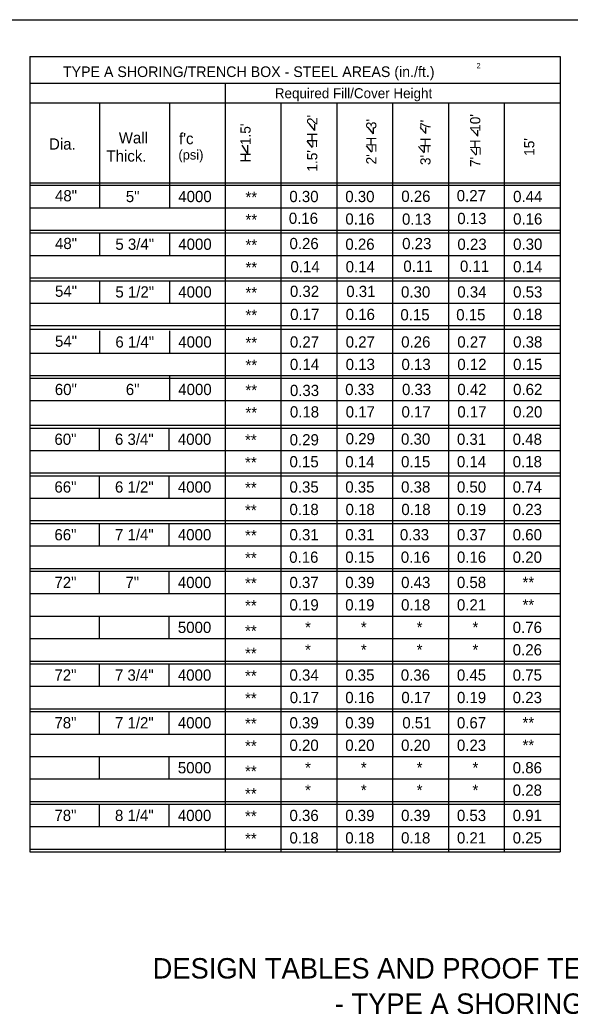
# Model space of a CAD drawing. Extents: x -22562 to -18409, y 3991 to 7171.
# Drawn here: x -20178.4 to -20023, y 4289.5 to 4570.4 of the extents above; entities that cross this region are included whole.
import ezdxf

# ---------------------------------------------------------------- set-up
doc = ezdxf.new("R2010")
doc.units = 0
for name, color, linetype in [('1', 7, 'Continuous'), ('2', 7, 'Continuous'), ('3', 7, 'Continuous'), ('4', 7, 'Continuous')]:
    doc.layers.add(name, color=color, linetype=linetype)

msp = doc.modelspace()

# ---------------------------------------------------------------- linework, layer by layer
at = {"layer": '1'}
for p, q in [((-20095.05, 4539.1), (-20096.61, 4540.87)), ((-20095.05, 4539.1), (-20095.05, 4540.86)), ((-20078.47, 4538.16), (-20080.04, 4539.93)), ((-20078.47, 4538.16), (-20078.47, 4539.92)), ((-20063.73, 4538.22), (-20065.3, 4539.99)), ((-20063.73, 4538.22), (-20063.73, 4539.97)), ((-20049.01, 4537.47), (-20050.58, 4539.24)), ((-20049.01, 4537.47), (-20049.01, 4539.22)), ((-20114.01, 4532.54), (-20115.57, 4534.97)), ((-20114.01, 4532.54), (-20114.01, 4534.95)), ((-20095.7, 4534.3), (-20097.27, 4536.07)), ((-20078.93, 4533.02), (-20080.49, 4534.79)), ((-20064.19, 4532.8), (-20065.75, 4534.57)), ((-20049.47, 4532.11), (-20051.03, 4533.87))]:
    msp.add_line(p, q, dxfattribs=at)
at = {"layer": '2'}
for p, q in [((-20344.85, 4570.37), (-19558.85, 4570.37)), ((-20175.6, 4560.02), (-20175.6, 4335.28)), ((-20175.6, 4560.02), (-20025.8, 4560.02)), ((-20025.8, 4560.02), (-20025.8, 4335.28)), ((-20175.6, 4552.45), (-20025.8, 4552.45)), ((-20120.41, 4552.45), (-20120.41, 4335.28)), ((-20175.6, 4546.95), (-20025.8, 4546.95)), ((-20155.88, 4546.95), (-20155.88, 4520.26)), ((-20136.17, 4546.95), (-20136.17, 4520.15)), ((-20104.64, 4546.95), (-20104.64, 4335.28)), ((-20088.87, 4546.95), (-20088.87, 4335.28)), ((-20073.1, 4546.95), (-20073.1, 4335.28)), ((-20057.34, 4546.95), (-20057.34, 4335.28)), ((-20041.57, 4546.95), (-20041.57, 4335.28)), ((-20175.6, 4524.43), (-20175.6, 4415.32)), ((-20175.6, 4524.37), (-20025.8, 4524.37)), ((-20175.6, 4523.68), (-20025.8, 4523.68)), ((-20155.88, 4524.43), (-20155.88, 4517.3)), ((-20155.88, 4523.64), (-20155.88, 4517.3)), ((-20136.17, 4524.43), (-20136.17, 4517.3)), ((-20136.17, 4523.64), (-20136.17, 4517.3)), ((-20175.6, 4517.3), (-20025.8, 4517.3)), ((-20175.6, 4510.95), (-20025.8, 4510.95)), ((-20175.6, 4510.95), (-20025.8, 4510.95)), ((-20175.6, 4510.16), (-20025.8, 4510.16)), ((-20155.88, 4510.16), (-20155.88, 4503.82)), ((-20136.17, 4510.16), (-20136.17, 4503.82)), ((-20175.6, 4503.82), (-20025.8, 4503.82)), ((-20175.6, 4497.47), (-20025.8, 4497.47)), ((-20175.6, 4497.47), (-20025.8, 4497.47)), ((-20175.6, 4496.68), (-20025.8, 4496.68)), ((-20155.88, 4496.68), (-20155.88, 4490.33)), ((-20136.17, 4496.68), (-20136.17, 4490.33)), ((-20175.6, 4490.33), (-20025.8, 4490.33)), ((-20175.6, 4483.99), (-20025.8, 4483.99)), ((-20175.6, 4483.99), (-20025.8, 4483.99)), ((-20175.45, 4483.02), (-20025.65, 4483.02)), ((-20155.88, 4482.55), (-20155.88, 4476.2)), ((-20136.17, 4482.55), (-20136.17, 4476.2)), ((-20175.6, 4476.2), (-20025.8, 4476.2)), ((-20175.6, 4469.86), (-20025.8, 4469.86)), ((-20175.6, 4469.86), (-20025.8, 4469.86)), ((-20136.17, 4469.92), (-20136.17, 4462.79)), ((-20175.6, 4469.17), (-20025.8, 4469.17)), ((-20175.6, 4462.79), (-20025.79, 4462.79)), ((-20175.71, 4455.85), (-20025.91, 4455.85)), ((-20175.71, 4455.06), (-20025.91, 4455.06)), ((-20156, 4455.06), (-20156, 4448.71)), ((-20136.29, 4455.06), (-20136.29, 4448.71)), ((-20175.71, 4448.71), (-20025.91, 4448.71)), ((-20175.71, 4442.37), (-20025.91, 4442.37)), ((-20175.71, 4442.36), (-20025.91, 4442.36)), ((-20175.71, 4441.57), (-20175.71, 4441.57)), ((-20175.71, 4441.57), (-20025.91, 4441.57)), ((-20156, 4441.57), (-20156, 4435.23)), ((-20136.29, 4441.57), (-20136.29, 4435.23)), ((-20175.71, 4435.23), (-20025.91, 4435.23)), ((-20175.71, 4428.88), (-20025.91, 4428.88)), ((-20175.71, 4428.88), (-20025.91, 4428.88)), ((-20175.71, 4428.08), (-20025.91, 4428.08)), ((-20156, 4428.08), (-20156, 4421.74)), ((-20136.29, 4428.08), (-20136.29, 4421.74)), ((-20175.71, 4421.74), (-20025.91, 4421.74)), ((-20175.71, 4415.39), (-20025.91, 4415.39)), ((-20175.71, 4415.39), (-20025.91, 4415.39)), ((-20175.71, 4414.6), (-20025.91, 4414.6)), ((-20156, 4414.6), (-20156, 4408.26)), ((-20136.29, 4414.6), (-20136.29, 4408.26)), ((-20175.71, 4408.26), (-20025.91, 4408.26)), ((-20175.71, 4401.91), (-20025.91, 4401.91)), ((-20156, 4401.91), (-20156, 4395.57)), ((-20136.29, 4401.91), (-20136.29, 4395.57)), ((-20175.71, 4395.57), (-20025.91, 4395.57)), ((-20175.71, 4389.22), (-20025.91, 4389.22)), ((-20175.71, 4389.22), (-20025.91, 4389.22)), ((-20175.71, 4388.43), (-20025.91, 4388.43)), ((-20156, 4388.43), (-20156, 4382.09)), ((-20136.29, 4388.43), (-20136.29, 4382.09)), ((-20175.71, 4382.09), (-20025.91, 4382.09)), ((-20175.71, 4375.74), (-20025.91, 4375.74)), ((-20175.71, 4375.74), (-20025.91, 4375.74)), ((-20175.71, 4374.95), (-20025.91, 4374.95)), ((-20156, 4374.95), (-20156, 4368.6)), ((-20136.29, 4374.95), (-20136.29, 4368.6)), ((-20175.71, 4368.6), (-20025.91, 4368.6)), ((-20175.71, 4362.26), (-20025.91, 4362.26)), ((-20156, 4362.26), (-20156, 4355.91)), ((-20136.29, 4362.26), (-20136.29, 4355.91)), ((-20175.71, 4355.91), (-20025.91, 4355.91)), ((-20175.71, 4349.56), (-20025.91, 4349.56)), ((-20175.71, 4349.56), (-20025.91, 4349.56)), ((-20175.71, 4348.78), (-20025.91, 4348.78)), ((-20156, 4348.78), (-20156, 4342.43)), ((-20136.29, 4348.78), (-20136.29, 4342.43)), ((-20175.71, 4342.43), (-20025.91, 4342.43)), ((-20175.71, 4336.08), (-20025.91, 4336.08)), ((-20175.6, 4335.28), (-20025.8, 4335.28))]:
    msp.add_line(p, q, dxfattribs=at)

# ---------------------------------------------------------------- texts
at = {"layer": '1'}
for s, height, p in [("f'c", 3.172, (-20133.46, 4535.24)), ('Thick.', 3.172, (-20153.95, 4530.33)), ('(psi)', 2.719, (-20133.62, 4530.9)), ('DESIGN TABLES AND PROOF TEST LOAD TABLE FOR CIRCULAR PIPES', 5.7669, (-20140.9, 4299.52)), ('- TYPE A SHORING/TRENCH BOX INSTALLATION', 5.7669, (-20089.43, 4289.54))]:
    msp.add_text(s, height=height, dxfattribs=at).set_placement(p)
for s, height, p in [("15'", 2.883, (-20033.06, 4531.95)), ('=', 2.88, (-20093.76, 4534.27)), ('=', 2.88, (-20076.98, 4532.99)), ('=', 2.88, (-20062.24, 4532.78)), ('=', 2.88, (-20047.52, 4532.08))]:
    msp.add_text(s, height=height, rotation=90, dxfattribs=at).set_placement(p)
at = {"layer": '2'}
for s, height, p in [('TYPE A SHORING/TRENCH BOX - STEEL AREAS (in./ft.)', 3, (-20166.25, 4554.22)), ('2', 1.5, (-20049.39, 4556.67)), ('Required Fill/Cover Height', 2.8357, (-20106.38, 4548.23)), ('Dia.', 3.172, (-20170.18, 4533.71)), ('Wall', 3.172, (-20150.47, 4535.46))]:
    msp.add_text(s, height=height, dxfattribs=at).set_placement(p)
at = {"layer": '3'}
for s, height, p in [('**', 3.173, (-20114.68, 4518.67)), ('0.30', 3.172, (-20102.28, 4518.88)), ('0.30', 3.172, (-20086.48, 4518.88)), ('0.26', 3.172, (-20070.65, 4518.95)), ('0.27', 3.174, (-20054.99, 4519.13)), ('0.44', 3.173, (-20039.06, 4518.88)), ('**', 3.173, (-20114.68, 4512.32)), ('0.16', 3.172, (-20102.43, 4512.73)), ('0.16', 3.172, (-20086.45, 4512.54)), ('0.13', 3.173, (-20070.45, 4512.49)), ('0.13', 3.173, (-20054.84, 4512.67)), ('0.16', 3.173, (-20039.06, 4512.54)), ('0.26', 3.172, (-20102.24, 4505.59)), ('0.26', 3.172, (-20086.45, 4505.4)), ('0.23', 3.174, (-20070.41, 4505.58)), ('0.23', 3.174, (-20054.8, 4505.39)), ('0.30', 3.173, (-20039.06, 4505.4)), ('**', 3.173, (-20114.68, 4505.18)), ('**', 3.173, (-20114.68, 4498.83)), ('0.14', 3.172, (-20101.97, 4499.05)), ('0.14', 3.172, (-20086.37, 4499.05)), ('0.11', 3.173, (-20070.07, 4499.18)), ('0.11', 3.173, (-20054.09, 4499.18)), ('0.14', 3.174, (-20039.06, 4499.05)), ('**', 3.173, (-20114.68, 4491.7)), ('0.32', 3.172, (-20102.12, 4492.09)), ('0.31', 3.173, (-20086.2, 4492.06)), ('0.30', 3.172, (-20070.73, 4491.92)), ('0.34', 3.173, (-20054.83, 4491.92)), ('0.53', 3.173, (-20039.06, 4491.92)), ('**', 3.173, (-20114.68, 4485.35)), ('0.17', 3.172, (-20102.05, 4485.57)), ('0.16', 3.173, (-20086.36, 4485.57)), ('0.15', 3.173, (-20070.9, 4485.47)), ('0.15', 3.173, (-20055.13, 4485.47)), ('0.18', 3.173, (-20039.06, 4485.57)), ('**', 3.173, (-20114.68, 4477.57)), ('0.27', 3.173, (-20102.13, 4477.79)), ('0.27', 3.173, (-20086.36, 4477.79)), ('0.26', 3.172, (-20070.68, 4477.79)), ('0.27', 3.173, (-20054.83, 4477.79)), ('0.27', 3.173, (-20054.83, 4477.79)), ('0.38', 3.173, (-20039.06, 4477.79)), ('**', 3.173, (-20114.68, 4471.22)), ('0.14', 3.172, (-20102.13, 4471.44)), ('0.13', 3.173, (-20086.36, 4471.44)), ('0.13', 3.172, (-20070.6, 4471.44)), ('0.12', 3.173, (-20054.83, 4471.44)), ('0.15', 3.173, (-20039.06, 4471.44)), ('**', 3.173, (-20114.69, 4464.15)), ('0.33', 3.172, (-20102.12, 4464.09)), ('0.33', 3.172, (-20086.5, 4464.37)), ('0.33', 3.172, (-20070.45, 4464.37)), ('0.42', 3.173, (-20054.82, 4464.37)), ('0.62', 3.173, (-20039.06, 4464.37)), ('**', 3.173, (-20114.69, 4457.81)), ('0.18', 3.172, (-20102.13, 4458.03)), ('0.17', 3.172, (-20086.36, 4458.03)), ('0.17', 3.172, (-20070.59, 4458.03)), ('0.17', 3.173, (-20054.82, 4458.03)), ('0.20', 3.173, (-20039.06, 4458.03)), ('**', 3.173, (-20114.8, 4450.08)), ('0.29', 3.173, (-20102.19, 4450.15)), ('0.29', 3.173, (-20086.36, 4450.44)), ('0.30', 3.172, (-20070.73, 4450.34)), ('0.31', 3.173, (-20054.94, 4450.3)), ('0.48', 3.173, (-20039.17, 4450.3)), ('**', 3.173, (-20114.8, 4443.73)), ('0.15', 3.172, (-20102.24, 4443.95)), ('0.14', 3.172, (-20086.48, 4443.95)), ('0.15', 3.172, (-20070.71, 4443.95)), ('0.14', 3.173, (-20054.94, 4443.95)), ('0.18', 3.173, (-20039.17, 4443.95)), ('**', 3.173, (-20114.8, 4436.59)), ('0.35', 3.173, (-20102.24, 4436.81)), ('0.35', 3.173, (-20086.48, 4436.81)), ('0.38', 3.172, (-20070.71, 4436.81)), ('0.50', 3.173, (-20054.94, 4436.81)), ('0.74', 3.173, (-20039.17, 4436.81)), ('**', 3.173, (-20114.8, 4430.24)), ('0.18', 3.173, (-20102.24, 4430.46)), ('0.18', 3.173, (-20086.4, 4430.46)), ('0.18', 3.173, (-20070.63, 4430.46)), ('0.19', 3.173, (-20054.94, 4430.46)), ('0.23', 3.173, (-20039.17, 4430.46)), ('**', 3.173, (-20114.8, 4423.11)), ('0.31', 3.173, (-20102.24, 4423.32)), ('0.31', 3.173, (-20086.48, 4423.32)), ('0.33', 3.172, (-20071.05, 4423.32)), ('0.37', 3.173, (-20054.94, 4423.32)), ('0.60', 3.173, (-20039.17, 4423.32)), ('**', 3.173, (-20114.8, 4416.76)), ('0.16', 3.172, (-20102.32, 4416.98)), ('0.15', 3.173, (-20086.48, 4416.98)), ('0.16', 3.172, (-20070.79, 4416.98)), ('0.16', 3.173, (-20054.94, 4416.98)), ('0.20', 3.173, (-20039.17, 4416.98)), ('0.37', 3.172, (-20102.25, 4409.84)), ('0.39', 3.172, (-20086.48, 4409.84)), ('0.43', 3.172, (-20070.7, 4409.84)), ('0.58', 3.173, (-20054.94, 4409.84)), ('**', 3.173, (-20114.8, 4409.63)), ('**', 3.173, (-20036.41, 4409.84)), ('**', 3.173, (-20114.8, 4403.28)), ('0.19', 3.173, (-20102.24, 4403.5)), ('0.19', 3.173, (-20086.49, 4403.5)), ('0.18', 3.172, (-20070.71, 4403.5)), ('0.21', 3.173, (-20054.94, 4403.5)), ('**', 3.173, (-20036.41, 4403.5)), ('**', 3.173, (-20114.8, 4396.14)), ('*', 3.17, (-20097.84, 4397.15)), ('*', 3.17, (-20082.08, 4397.15)), ('*', 3.17, (-20066.31, 4397.15)), ('*', 3.17, (-20050.54, 4397.15)), ('0.76', 3.173, (-20039.17, 4397.15)), ('*', 3.17, (-20097.84, 4390.81)), ('*', 3.17, (-20082.08, 4390.81)), ('*', 3.17, (-20066.31, 4390.81)), ('*', 3.17, (-20050.54, 4390.81)), ('0.26', 3.173, (-20039.17, 4390.81)), ('**', 3.173, (-20114.8, 4389.79)), ('**', 3.173, (-20114.8, 4383.45)), ('0.34', 3.172, (-20102.24, 4383.67)), ('0.35', 3.173, (-20086.48, 4383.67)), ('0.36', 3.172, (-20070.79, 4383.67)), ('0.45', 3.173, (-20054.94, 4383.67)), ('0.75', 3.173, (-20039.17, 4383.67)), ('**', 3.173, (-20114.8, 4377.1)), ('0.17', 3.172, (-20102.16, 4377.32)), ('0.16', 3.173, (-20086.48, 4377.32)), ('0.17', 3.172, (-20070.63, 4377.32)), ('0.19', 3.173, (-20054.93, 4377.32)), ('0.23', 3.173, (-20039.17, 4377.32)), ('**', 3.173, (-20114.8, 4369.97)), ('0.39', 3.173, (-20102.24, 4370.19)), ('0.39', 3.172, (-20086.49, 4370.19)), ('0.51', 3.172, (-20070.37, 4370.19)), ('0.67', 3.173, (-20054.94, 4370.19)), ('**', 3.173, (-20036.41, 4370.19)), ('**', 3.173, (-20114.8, 4363.62)), ('0.20', 3.173, (-20102.24, 4363.84)), ('0.20', 3.173, (-20086.48, 4363.84)), ('0.20', 3.173, (-20070.71, 4363.84)), ('0.23', 3.173, (-20054.94, 4363.84)), ('**', 3.173, (-20036.41, 4363.84)), ('*', 3.17, (-20097.84, 4357.49)), ('*', 3.17, (-20082.08, 4357.49)), ('*', 3.17, (-20066.31, 4357.49)), ('*', 3.17, (-20050.54, 4357.49)), ('0.86', 3.173, (-20039.17, 4357.49)), ('**', 3.173, (-20114.8, 4356.48)), ('*', 3.17, (-20097.84, 4351.15)), ('*', 3.17, (-20082.08, 4351.15)), ('*', 3.17, (-20066.31, 4351.15)), ('*', 3.17, (-20050.54, 4351.15)), ('0.28', 3.173, (-20039.17, 4351.15)), ('**', 3.173, (-20114.8, 4350.13)), ('**', 3.173, (-20114.8, 4343.79)), ('0.36', 3.172, (-20102.24, 4344.01)), ('0.39', 3.173, (-20086.48, 4344.01)), ('0.39', 3.173, (-20070.71, 4344.01)), ('0.53', 3.173, (-20054.94, 4344.01)), ('0.91', 3.173, (-20039.17, 4344.01)), ('**', 3.173, (-20114.8, 4337.45)), ('0.18', 3.173, (-20102.24, 4337.67)), ('0.18', 3.173, (-20086.48, 4337.67)), ('0.18', 3.173, (-20070.71, 4337.67)), ('0.21', 3.173, (-20054.94, 4337.67)), ('0.25', 3.173, (-20039.17, 4337.67))]:
    msp.add_text(s, height=height, dxfattribs=at).set_placement(p)
at = {"layer": '4'}
for s, height, p in [("1.5'  H  2'", 2.8834, (-20094.37, 4527.49)), ("7'  H  10'", 2.883, (-20048.33, 4528.79)), ("H  1.5'", 2.883, (-20113.22, 4530.06)), ("2'  H  3'", 2.883, (-20077.69, 4529.54)), ("3'  H  7'", 2.883, (-20062.4, 4529.33))]:
    msp.add_text(s, height=height, rotation=90, dxfattribs=at).set_placement(p)
for s, p in [('48"', (-20168.49, 4519.09)), ('5"', (-20148.48, 4518.88)), ('4000', (-20133.66, 4518.88)), ('48"', (-20168.49, 4505.61)), ('5 3/4"', (-20151.43, 4505.4)), ('4000', (-20133.66, 4505.4)), ('54"', (-20168.49, 4492.13)), ('5 1/2"', (-20151.43, 4491.92)), ('4000', (-20133.66, 4491.92)), ('54"', (-20168.49, 4478)), ('6 1/4"', (-20151.43, 4477.79)), ('4000', (-20133.66, 4477.79)), ('60"', (-20168.54, 4464.37)), ('6"', (-20148.48, 4464.37)), ('4000', (-20133.67, 4464.37)), ('60"', (-20168.65, 4450.3)), ('6 3/4"', (-20151.55, 4450.3)), ('4000', (-20133.78, 4450.3)), ('66"', (-20168.65, 4436.81)), ('6 1/2"', (-20151.55, 4436.81)), ('4000', (-20133.78, 4436.81)), ('66"', (-20168.65, 4423.32)), ('7 1/4"', (-20151.55, 4423.32)), ('4000', (-20133.78, 4423.32)), ('72"', (-20168.65, 4409.84)), ('4000', (-20133.78, 4409.84)), ('7"', (-20148.59, 4409.84)), ('5000', (-20133.78, 4397.15)), ('72"', (-20168.65, 4383.67)), ('7 3/4"', (-20151.55, 4383.67)), ('4000', (-20133.78, 4383.67)), ('78"', (-20168.65, 4370.19)), ('7 1/2"', (-20151.55, 4370.19)), ('4000', (-20133.78, 4370.19)), ('5000', (-20133.78, 4357.49)), ('78"', (-20168.65, 4344.01)), ('8 1/4"', (-20151.55, 4344.01)), ('4000', (-20133.78, 4344.01))]:
    msp.add_text(s, height=3.173, dxfattribs=at).set_placement(p)

doc.saveas('drawing.dxf')
